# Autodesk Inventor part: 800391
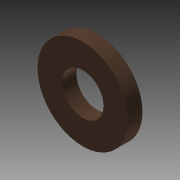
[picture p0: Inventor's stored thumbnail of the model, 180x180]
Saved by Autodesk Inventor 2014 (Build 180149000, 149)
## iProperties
Created: 2007-10
Part Number: 800391
Document SubType Name: Modeling
Designer: TC
Density: 7.85 g/cm^3
Mass: 5.27713 g
Surface Area: 7.0923 cm^2
Volume: 0.672246 cm^3
Material: Steel
Description: SHIM 8.7 MM X 3 MM
Appearance: Bronze - Satin
Component Category: Fasteners
Author: TC
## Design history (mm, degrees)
sketch "Sketch1"
  geometry: L1 (0, -2.1)-(0, 2.1) reference; L2 (-1.9, 0)-(11.4, 0) reference; L3 (4.35, 1.5)-(4.35, -1.5); L4 (4.35, -1.5)-(9.5, -1.5); L5 (9.5, -1.5)-(9.5, 1.5); L6 (9.5, 1.5)-(4.35, 1.5); 2 further points
  constraints: 8 end point, 2 parallel, 2 perpendicular, 1 midpoint, 1 point on line
  dimensions: "d0" = 8.7 diameter of L3 L1; "d1" = 19 diameter of L5 L1; "d2" = 3 distance between parallel lines of L4 L6
revolve "Revolution1" sketch "Sketch1" stored, may be unused: angle "d3" = 90 deg
body "Solid1"
